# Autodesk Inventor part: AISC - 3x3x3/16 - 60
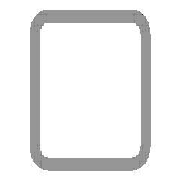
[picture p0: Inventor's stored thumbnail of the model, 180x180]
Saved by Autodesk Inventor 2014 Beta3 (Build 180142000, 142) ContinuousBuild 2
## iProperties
IsCustomPart: 1
Created: 2011-01
Part Number: AISC - 3x3x3/16 - 60
Material: Steel, Mild
Description: Tube
Document SubType Name: Modeling
Standard: ANSI
Designer: Beta-8540w
Standards Organization: ANSI
Language: en-US
Size Designation: 3x3x3/16
Categories: <MemberInstance><Categories><Category DisplayName="Structural Shapes" InternalName="089c4875-fa83-4c05-b084-43b9cc11f5ed" Mnemonic="GRDR"><CategoryParameter Dis
Stock Number: 3x3x3/16
Density: 7.86 g/cm^3
Appearance: Steel
_CCFamilyMember: 9
_CCFamilyDisplayName: ANSI AISC (Square) - Tube
_FrameMemberDoc: Frame Member File
_Version: 15.0.0
_GetPNFromCC: 1
G_L: 60.000 in
G_W: 3.000 in
G_H: 3.000 in
Author: Beta-8540w
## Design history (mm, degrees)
node "Start plane"
node "End plane"
sketch "Sketch"
  geometry: L1 (-38.1, -28.575)-(-38.1, 28.575); L2 (-28.575, 38.1)-(28.575, 38.1); L3 (38.1, 28.575)-(38.1, -28.575); L4 (28.575, -38.1)-(-28.575, -38.1); L5 (-28.575, 33.337)-(28.575, 33.338); L6 (33.338, 28.575)-(33.338, -28.575); L7 (28.575, -33.337)-(-28.575, -33.338); L8 (-33.338, -28.575)-(-33.338, 28.575); L9 (0, 56.102)-(0, -56.102) reference; L10 (-56.102, 0)-(56.102, 0) reference; A1 r 9.525 centre (-28.575, -28.575) between (-38.1, -28.575) and (-28.575, -38.1); A2 r 9.525 centre (-28.575, 28.575) between (-28.575, 38.1) and (-38.1, 28.575); A3 r 9.525 centre (28.575, 28.575) between (38.1, 28.575) and (28.575, 38.1); A4 r 9.525 centre (28.575, -28.575) between (28.575, -38.1) and (38.1, -28.575); A5 r 4.763 centre (-28.575, 28.575) between (-28.575, 33.337) and (-33.338, 28.575); A6 r 4.763 centre (28.575, 28.575) between (33.338, 28.575) and (28.575, 33.338); A7 r 4.763 centre (28.575, -28.575) between (28.575, -33.337) and (33.338, -28.575); A8 r 4.763 centre (-28.575, -28.575) between (-33.338, -28.575) and (-28.575, -33.338)
  constraints: 16 end point, 16 point on circle, 8 centre point, 8 tangent, 4 parallel, 3 equal radius, 2 perpendicular, 7 other
  dimensions: "d10" = 76.2 distance between parallel lines of L2 L4 (= G_H); "d11" = 76.2 distance between parallel lines of L1 L3 (= G_W); "d12" = 4.7625 distance between parallel lines of L3 L6 (= G_T); "d15" = 38.1 distance between parallel lines of L2 L10 (= 0.5 x d10); "d16" = 38.1 distance between parallel lines of L9 L3 (= 0.5 x d11); "d17" = 9.525 radius of A1 (= G_IR)
extrude "Body" new body sketch "Sketch" stored distance "d3" = 1524 (= G_L); taper "d4" = 0 deg
node "Driven Length"
  sketch "Sketch3"
    geometry: L1 (0, 0)-(10, 0) reference
    constraints: 2 end point, 1 horizontal
  workplane "Work Plane3"
  sketch "Sketch4"
    geometry: L1 (-2, 0)-(12, 0) reference; L2 (-2, 1524)-(12, 1524) reference
    dimensions: "d19" = 1524 distance between parallel lines of L1 L2 (derived)
body "Solid1"
other parameters: "G_W" = 76.2 [user parameter; used in 1 equation term], "G_H" = 76.2 [user parameter; used in 1 equation term], "G_T" = 4.7625 [user parameter; used in 1 equation term], "G_IR" = 9.525 [user parameter; used in 1 equation term], "G_L" = 1524 (= d19) [user parameter; used in 1 equation term], "G_OFFSET_START" = 0 [user parameter; used in 1 equation term], "G_OFFSET_END" = 0 [user parameter; used in 1 equation term], "d13" = 0 (computed from G_OFFSET_START), "d14" = 1524 (= G_OFFSET_END + B_L), "B_L" = 1524 [user parameter; used in 1 equation term], "d18" = 90 deg
